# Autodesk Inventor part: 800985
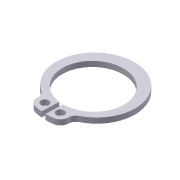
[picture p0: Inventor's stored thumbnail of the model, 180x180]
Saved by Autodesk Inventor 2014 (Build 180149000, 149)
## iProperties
Created: 2007-03
Part Number: 800985
Material: Steel, High Strength Low Alloy
Description: RETAINING RING 12 X 1
Document SubType Name: Modeling
Standard: JIS B 2804
Designer: JJ
Standards Organization: JIS
Language: en-US
Size Designation: 12x1
Categories: <MemberInstance><Categories><Category DisplayName="Shaft Parts" InternalName="7f7aeb1f-a693-4053-b835-cee3144e0d98" Mnemonic="SHFT"><Category DisplayName="Circl
Density: 7.84 g/cm^3
Mass: 0.565729 g
Surface Area: 2.44204 cm^2
Volume: 0.0721593 cm^3
Appearance: Glossy - Black
Component Category: Fasteners
IsCustomPart: 0
Author: JJ
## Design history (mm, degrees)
sketch "Sketch1"
  geometry: L1 (-6, 0)-(6, 0) reference; L2 (0, 5.156)-(0, -18.338) reference; L3 (-10.29, 0)-(10.29, 0) reference; L4 (-0.375, -11.738)-(-0.375, -14.938); L5 (-0.375, -6.54)-(-0.375, -13.29); L6 (-2.795, 1.8)-(3.672, 1.8); L7 (0.375, -6.54)-(0.375, -13.29); L8 (0.375, -11.738)-(0.375, -14.938); C1 r 0.75 at (-1.5, -13.293); C2 r 0.75 at (1.5, -13.293); A1 r 5.75 centre (0, -6) between (0.375, -11.738) and (-0.375, -11.738); A2 r 7.35 centre (0, -5.55) between (3.735, -11.88) and (-3.735, -11.88); A3 r 8.946 centre (0, -6) between (-1.802, -14.762) and (-0.375, -14.938); A4 r 1.5 centre (-1.5, -13.293) between (-2.999, -13.232) and (-1.802, -14.762); A5 r 1.5 centre (-4.498, -13.172) between (-2.999, -13.232) and (-3.735, -11.88); A6 r 1.5 centre (4.498, -13.172) between (3.735, -11.88) and (2.999, -13.232); A7 r 1.5 centre (1.5, -13.293) between (1.802, -14.762) and (2.999, -13.232); A8 r 8.946 centre (0, -6) between (0.375, -14.938) and (1.802, -14.762)
  constraints: 16 point on circle, 12 end point, 10 centre point, 9 symmetric about line, 5 point on line, 4 tangent, 3 coincident, 2 horizontal, 1 perpendicular, 1 vertical, 5 other
  dimensions: "d0" = 11.5 diameter of A1 (= ND); "d1" = 3.2 distance of L4.end L4.start (= SRB2); "d6" = 0.375 distance between parallel lines of L2 L5 (= 0.25 x SD5); "d7" = 1.8 distance between parallel lines of L6 L3 (= SRB1); "d8" = 0.45 distance of A1.centre A2.centre (= 0.25 x SRB1); "d9" = 1.5 radius of A4 (= SD5); "d10" = 1.5 radius of A5 (= SD5); "d11" = 1.125 distance from line of L4 A4.centre (= 0.75 x SD5); "d12" = 1.5 diameter of C1 (= SD5); "d13" = 1.5 diameter of C2 (= SD5); "d14" = 6 distance from line of A1.centre L1 (= 0.5 x WD)
extrude "Body" new body sketch "Sketch1" distance "d2" = 1 (= SD); taper "d3" = 0 deg
workaxis "Work Axis1"
workplane "Work Plane1"
body "Solid1"
other parameters: "WD" = 12 (= WDMIN) [user parameter; used in 1 equation term], "SD" = 1 [user parameter; used in 1 equation term], "SRB1" = 1.8 [user parameter; used in 2 equation terms], "ND" = 11.5 [user parameter; used in 1 equation term], "SRB2" = 3.2 [user parameter; used in 1 equation term], "SD5" = 1.5 [user parameter; used in 6 equation terms], "d15" = 0, "d16" = 0, "d17" = 0, "d41" = 0, "d42" = 0, "WDMIN" = 12 [user parameter; used in 1 equation term], "SD3" = 11.1 [user parameter], "WDMAX" = 13 [user parameter]
